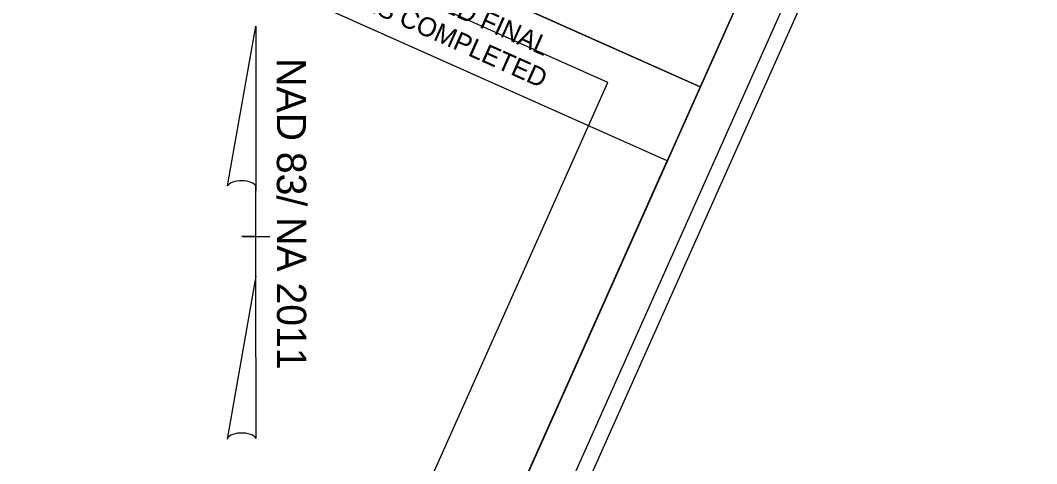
# Model space of a CAD drawing. Extents: x 2297991 to 2299183, y 599186 to 600200.
# Drawn here: x 2299005.9 to 2299182.8, y 599616.9 to 599694 of the extents above; entities that cross this region are included whole.
import ezdxf

# ---------------------------------------------------------------- set-up
doc = ezdxf.new("R2010")
doc.units = 0
for name, color, linetype in [('Exist DTM Drainline Cogo Comment', 7, 'Continuous'), ('Exist DTM Drainline Cogo Elevation', 7, 'Continuous'), ('Exist DTM Drainline Cogo Number', 7, 'Continuous'), ('Exist DTM Drainline Cogo Point CELL', 7, 'Continuous'), ('Exist Property Iron Pin CELL', 7, 'Continuous'), ('Exist Roads Curbs Cogo Elevation', 7, 'Continuous'), ('Exist Roads Curbs Cogo Number', 7, 'Continuous'), ('Exist Roads EOP Cogo Comment', 7, 'Continuous')]:
    doc.layers.add(name, color=color, linetype=linetype)

msp = doc.modelspace()

# ---------------------------------------------------------------- linework, layer by layer
at = {"layer": 'Exist DTM Drainline Cogo Comment'}
msp.add_lwpolyline([(2298345.56, 600145.92), (2298088.78, 599570.64), (2298910.61, 599203.78), (2299118.52, 599669.59), (2299008.92, 599718.52), (2299057.79, 599827.99)], close=True, dxfattribs=at)
at = {"layer": 'Exist DTM Drainline Cogo Elevation'}
msp.add_lwpolyline([(2299182.82, 599788.6), (2298260.17, 600200.46), (2297991.14, 599597.77), (2298913.79, 599185.92)], close=True, dxfattribs=at)
at = {"layer": 'Exist DTM Drainline Cogo Number'}
msp.add_lwpolyline([(2299174.87, 599777.4), (2298261.8, 600184.98), (2298003.76, 599606.9), (2298916.82, 599199.32)], close=True, dxfattribs=at)
at = {"layer": 'Exist DTM Drainline Cogo Point CELL'}
msp.add_lwpolyline([(2299167.39, 599779.06), (2298345.56, 600145.92), (2298088.76, 599570.63), (2298910.59, 599203.77)], close=True, dxfattribs=at)
at = {"layer": 'Exist Property Iron Pin CELL'}
for p, q in [((2299042, 599665.23), (2299046.92, 599693.04)), ((2299046.95, 599693.04), (2299046.95, 599664.36)), ((2299046.95, 599649.48), (2299046.95, 599665.2)), ((2299046.95, 599664.36), (2299046.95, 599665.17)), ((2299044.55, 599656.44), (2299044.52, 599656.44)), ((2299046.68, 599656.44), (2299044.55, 599656.44)), ((2299044.58, 599656.44), (2299049.38, 599656.44)), ((2299046.95, 599649.48), (2299041.94, 599621.13)), ((2299046.98, 599621.25), (2299046.95, 599649.48))]:
    msp.add_line(p, q, dxfattribs=at)
for centre, start_param, end_param in [((2299044.48, 599664.94), 0.216388, 2.908219), ((2299044.48, 599621.03), 0.201328, 3.141593)]:
    msp.add_ellipse(centre, major_axis=(2.54, -0.02), ratio=0.461098, start_param=start_param, end_param=end_param, dxfattribs=at)
at = {"layer": 'Exist Roads Curbs Cogo Elevation'}
msp.add_lwpolyline([(2299021.09, 599745.77), (2299130.67, 599696.86), (2299124.25, 599682.48), (2299014.67, 599731.39)], close=True, dxfattribs=at)
at = {"layer": 'Exist Roads Curbs Cogo Number'}
for p, q in [((2299014.67, 599731.39), (2299124.27, 599682.47)), ((2299118.52, 599669.59), (2299008.92, 599718.52)), ((2299124.27, 599682.46), (2299118.52, 599669.59))]:
    msp.add_line(p, q, dxfattribs=at)
at = {"layer": 'Exist Roads EOP Cogo Comment'}
msp.add_lwpolyline([(2298353.14, 600126.1), (2298108.59, 599578.22), (2298903.03, 599223.59), (2299108.19, 599683.24), (2298998.59, 599732.16), (2299037.98, 599820.4)], close=True, dxfattribs=at)

# ---------------------------------------------------------------- texts
at = {"layer": 'Exist Property Iron Pin CELL'}
msp.add_text('NAD 83/ NA 2011', height=5.1, rotation=270.0239, dxfattribs=at).set_placement((2299050.58, 599687.45))
at = {"layer": 'Exist Roads Curbs Cogo Number'}
for s, p in [('DOCUMENT NOT CONSIDERED FINAL', (2299023.68, 599720.57)), ('UNLESS ALL SIGNATURES COMPLETED', (2299018.75, 599716.99))]:
    msp.add_text(s, height=3.3, rotation=335.9448, dxfattribs=at).set_placement(p)

doc.saveas('drawing.dxf')
